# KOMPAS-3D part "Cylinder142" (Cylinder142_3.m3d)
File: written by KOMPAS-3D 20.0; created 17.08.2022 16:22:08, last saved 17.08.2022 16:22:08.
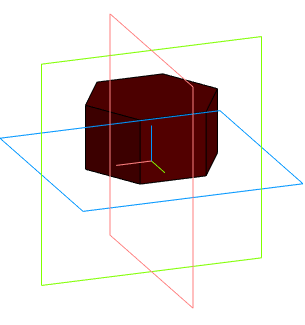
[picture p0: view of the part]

Document properties: Автор: artemsv220@gmail.com; Полное имя файла: \\192.168.2.25\новая общая папка\Медиа\Светильники\Кашпо\Кашпо и вазоны\DWG\Cylinder142_3.m3d

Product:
- Part/product: Cylinder142

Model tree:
1. Операция без истории:1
